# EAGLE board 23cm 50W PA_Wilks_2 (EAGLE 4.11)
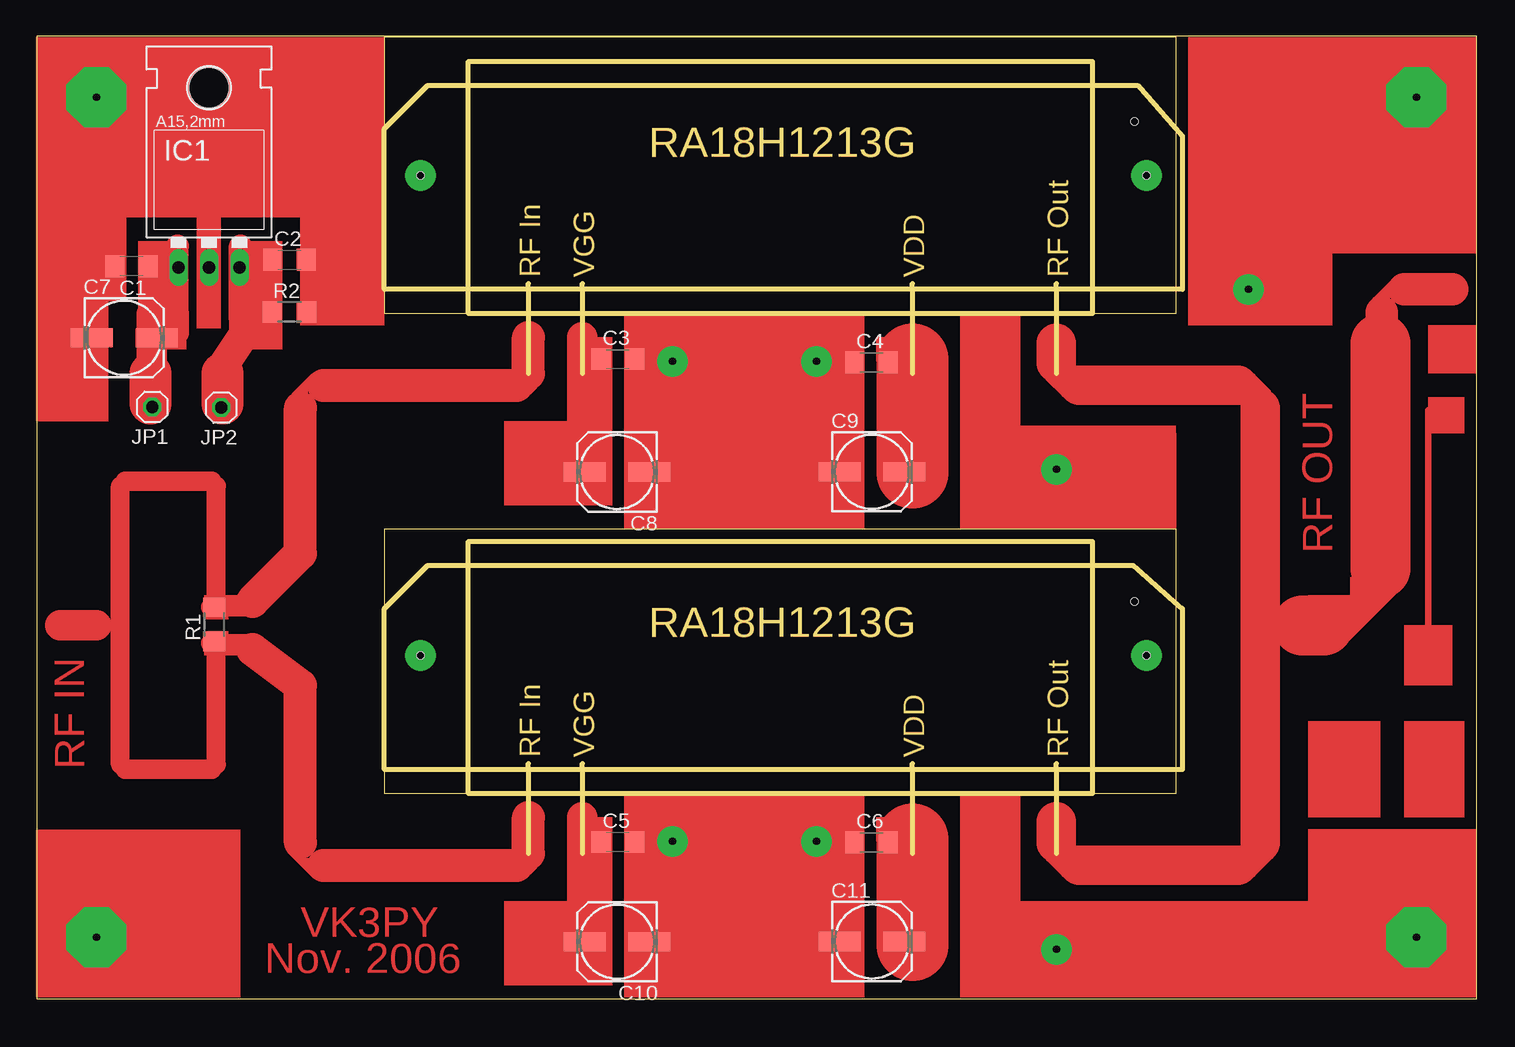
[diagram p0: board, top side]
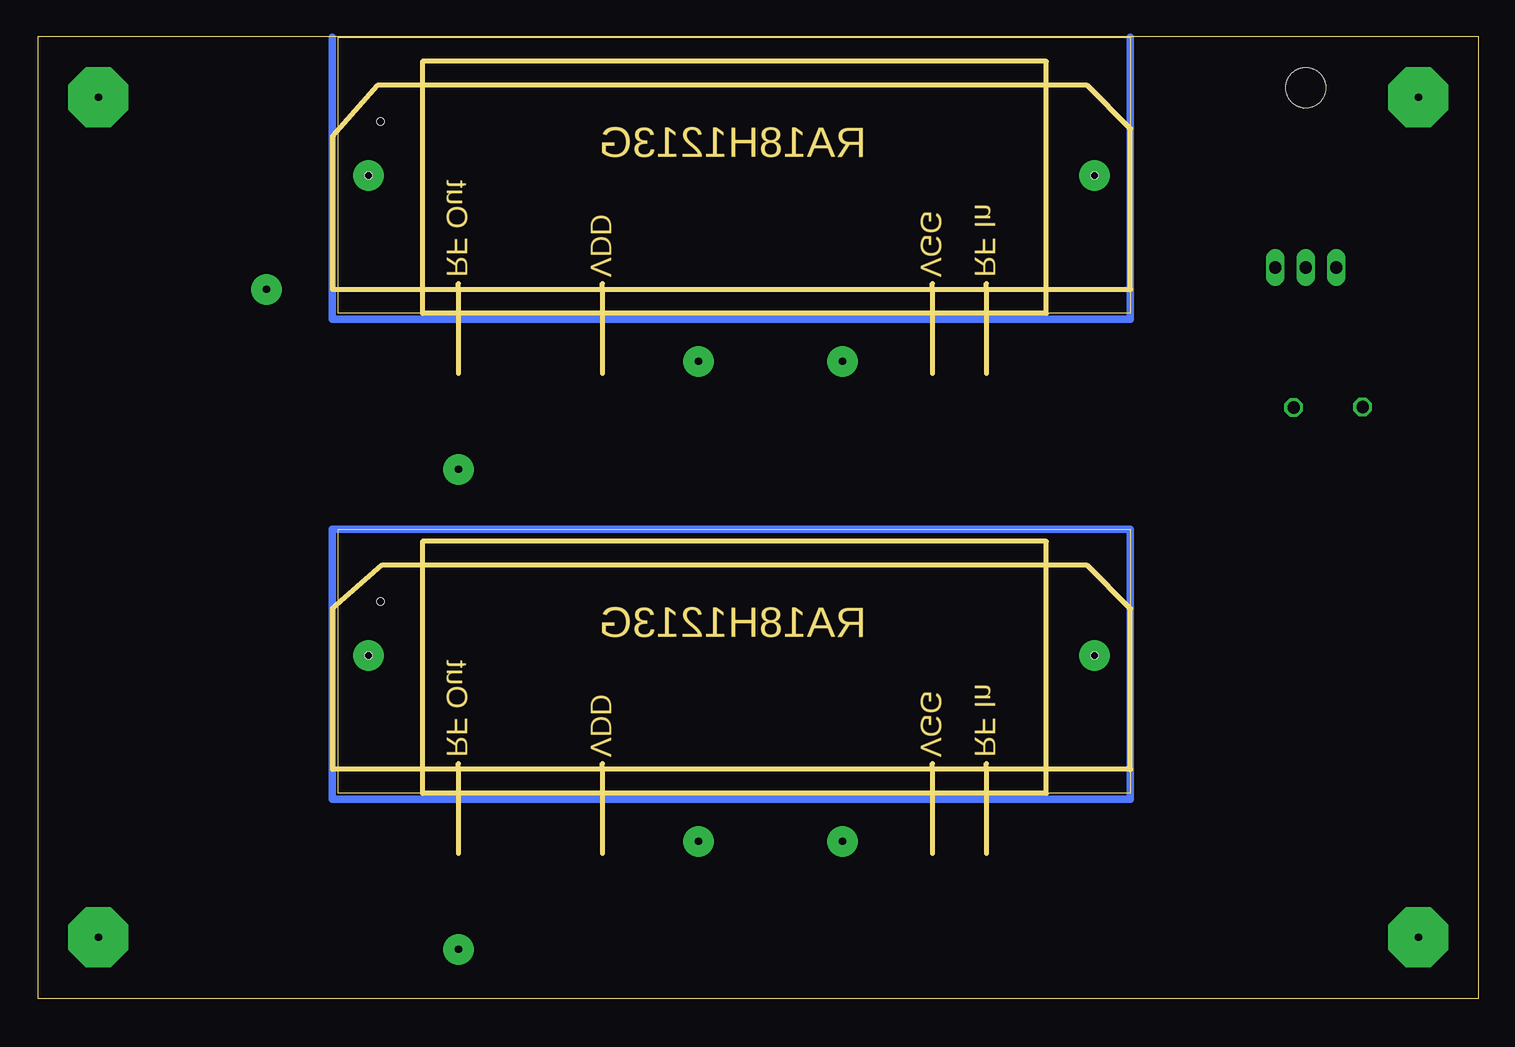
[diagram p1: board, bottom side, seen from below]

Size 120 x 80.23 mm. Coordinates in mm from the lower left corner, seen from the top.
Outline: 66 segments
Copper layers (1*16): Top 0.035mm / dielectric 1.5mm / Bottom 0.035mm
Design rules "default": minimum track width 10mil, minimum drill 24mil, track to track 8mil, track to pad 8mil, pad to pad 8mil, via to via 8mil, smd to smd 8mil, copper to edge 40mil, drill to drill 8mil, minimum pad ring 10mil, minimum via ring 8mil, stop-mask expansion 4mil, vias tented up to drill 0mil, thermal gap 10mil
Holes 0.61 mm at 31.97,68.63 92.47,68.63 91.47,73.13 91.47,33.13 92.47,28.63 31.97,28.63
Milling: area 29,57.1 to 95,80.1; area 29,17.1 to 95,39.1

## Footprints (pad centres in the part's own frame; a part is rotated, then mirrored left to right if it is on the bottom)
C1206 = smd 1.6 x 1.8: 1 -1.4,0; 2 1.4,0
153CLV-0605 = smd 3.5 x 1.6: + 2.7,0; - -2.7,0
78XXL = drill 1.016 long: GND 0,-3.81; IN -2.54,-3.81; OUT 2.54,-3.81 | hole 3.302: 0,11.176
1X01 = drill 1.016 octagon: 1 0,0
R1206 = smd 1.6 x 1.803: 1 -1.422,0; 2 1.422,0

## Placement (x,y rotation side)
C1  [C1206]  7.89,61.05 180 top
C2  [C1206]  21.05,61.59 0 top
C3  [C1206]  48.41,53.32 0 top
C4  [C1206]  69.55,53.05 0 top
C5  [C1206]  48.41,13.08 0 top
C6  [C1206]  69.55,13.05 0 top
C7  [153CLV-0605]  7.27,55.1 0 top
C8  [153CLV-0605]  48.35,43.91 180 top
C9  [153CLV-0605]  69.59,43.92 0 top
C10  [153CLV-0605]  48.35,4.77 180 top
C11  [153CLV-0605]  69.59,4.78 0 top
IC1  [78XXL]  14.35,64.75 0 top
JP1  [1X01]  9.62,49.33 180 top
JP2  [1X01]  15.37,49.28 180 top
R1  [R1206]  14.78,31.21 90 top
R2  [R1206]  21.05,57.25 0 top

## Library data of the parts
C1-C11 R1 R2 = rcl
IC1 = v-reg
JP1 JP2 = pinhead

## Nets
GND: C1.2 C2.2 IC1.GND
N$1: C1.1 IC1.IN JP1.1
N$2: C2.1 IC1.OUT JP2.1

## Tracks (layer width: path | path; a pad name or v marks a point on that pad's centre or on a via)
GND
  Top 0.406: 0.97,72.63 0.97,79.13 25.97,79.13 25.97,72.63 | 0.97,72.63 14.47,72.63 | 14.47,72.63 25.97,72.63 | IC1.GND 14.35,57.94 14.47,72.63 | 0.97,72.63 0.97,61.13 6.97,61.13 6.97,61.05 C1.2 | C2.2 25.97,61.59 25.97,72.63
N$1
  Top 0.406: 11.97,56.94 11.97,57.13 | 11.97,56.94 IC1.IN | 9.6,57.05 C1.1 | 9.6,57.05 11.97,56.05 11.97,56.94 | 9.6,57.05 9.85,57.13 | JP1.1 9.6,49.33
  Top 2.54: 9.6,49.33 9.6,57.05
N$2
  Top 0.406: 16.97,56.94 16.97,57.01 16.97,57.13 | 16.97,56.94 IC1.OUT | 16.97,56.59 18.34,56.59 18.37,61.63 18.97,61.59 C2.1 | 16.97,56.88 16.97,56.94 | JP2.1 15.35,49.28
  Top 1.93: 16.97,56.88 16.97,57.01 16.97,56.59 | 16.97,56.59 16.97,62.76 | 16.97,56.59 16.97,55.51
  Top 2.54: 15.35,49.28 15.47,49.13 15.47,49.63 | 15.47,52.13 15.47,52.63 18.47,57.13 18.97,56.59 18.34,56.59
  Top 3.5: 15.47,52.13 15.47,49.63
N$3
  Top 2.75: 21.97,49.23 21.97,37.13 17.97,33.13
N$4
  Top 2.75: 17.97,29.13 21.97,26.13 21.97,13.03
N$9
  Bottom 0.61: 28.97,80.13 28.97,56.63 95.47,56.63 95.47,80.13
N$13
  Top 5: 105.47,31.13 107.22,31.13
N$15
  Bottom 0.61: 28.97,16.63 28.97,39.13 95.47,39.13 95.47,16.63 28.97,16.63
N$16  (via drill 0.61 pad 2.54)
  other vias: 31.97,68.63
N$17  (via drill 0.61 pad 2.54)
  other vias: 31.97,28.63
N$18  (via drill 0.61 pad 2.54)
  other vias: 92.47,28.63
N$19  (via drill 0.61 pad 2.54)
  other vias: 92.47,68.63
N$20
  Top 3.3: 101.97,13.03 101.97,49.23
N$21
  Top 2.7: 111.97,53.13 112.07,57.23
  Top 5: 111.97,54.63 111.97,53.13 111.97,35.88
N$22
  Top 1.1: 108.47,29.63 113.47,34.63
N$23
  Top 2.7: 117.97,59.13 113.97,59.13
N$24
  Top 1.6: 14.97,33.13 14.97,42.73
N$25
  Top 1.6: 6.97,19.53 6.97,42.73
N$26
  Top 1.55: 17.47,32.63 14.47,32.63
N$27
  Top 1.55: 17.47,29.63 14.47,29.63
N$28
  Top 2.54: 4.97,31.13 1.97,31.13
N$29
  Top 0.54: 115.97,30.13 115.97,49.05
N$30
  Top 1.93: 11.72,56.88 11.72,57.13 | 11.72,57.13 11.72,62.76 | 11.72,57.13 11.72,55.51
N$31
  Top 6: 72.97,53.27 72.97,43.86 | 72.97,13.27 72.97,4.5
N$32
  Top 2.54: 45.47,55.13 45.47,44.13 | 45.47,15.13 45.47,4.13
N$33  (via drill 0.61 pad 2.54)
  other vias: 14.35,75.88
N$34  (via drill 0.61 pad 2.54)
  other vias: 52.97,53.13
N$35  (via drill 0.61 pad 2.54)
  other vias: 64.97,53.13
N$36  (via drill 0.61 pad 2.54)
  other vias: 52.97,13.13
N$37  (via drill 0.61 pad 2.54)
  other vias: 64.97,13.13 100.97,59.13
N$38  (via drill 0.61 pad 5)
  other vias: 114.97,5.13
N$39  (via drill 0.61 pad 5)
  other vias: 114.97,75.13
N$40  (via drill 0.61 pad 2.54)
  other vias: 84.97,4.13
N$41  (via drill 0.61 pad 2.54)
  other vias: 84.97,44.13
N$42
  Top 3.5: 9.47,52.13 9.47,49.63
N$43
  Top 3.3: 86.87,51.13 100.07,51.13
N$44
  Top 3.3: 84.97,53.03 84.97,54.63
N$45  (via drill 0.61 pad 5)
  other vias: 4.97,75.13
N$46  (via drill 0.61 pad 5)
  other vias: 4.97,5.13
N$47
  Top 3.3: 84.97,13.03 84.97,14.77
N$48
  Top 3.3: 86.87,11.13 100.07,11.13
N$49
  Top 2.75: 40.97,52.13 40.97,55.13
N$50
  Top 2.75: 40.97,12.13 40.97,15.13
N$51
  Top 2.75: 23.87,51.13 39.97,51.13
N$52
  Top 2.75: 23.87,11.13 39.97,11.13
N$53
  Top 1.6: 14.97,19.53 14.97,29.13
N$54
  Top 1.62: 7.37,19.13 14.57,19.13
N$55
  Top 1.62: 7.37,43.13 14.57,43.13
N$56
  Top 0.34: 84.17,51.73 85.57,50.33 | 101.37,10.33 102.87,11.83 | 101.37,51.93 102.67,50.63 | 84.27,11.63 85.57,10.33 | 21.27,12.03 22.87,10.43 | 21.37,50.33 22.97,51.93 | 41.07,10.53 41.57,11.03 | 41.07,50.53 41.57,51.03
  Top 0.58: 111.57,58.23 112.87,59.53
(copper drawn outside any net)
  shapes: Top area x82

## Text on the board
Top: RF OUT | RF IN | VK3PY | Nov. 2006
Dimension: RA18H1213G | RF In | VGG | VDD | RF Out | RA18H1213G | RF In | VGG | VDD | RF Out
